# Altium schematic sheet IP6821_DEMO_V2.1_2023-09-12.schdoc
size 298 x 183 mm
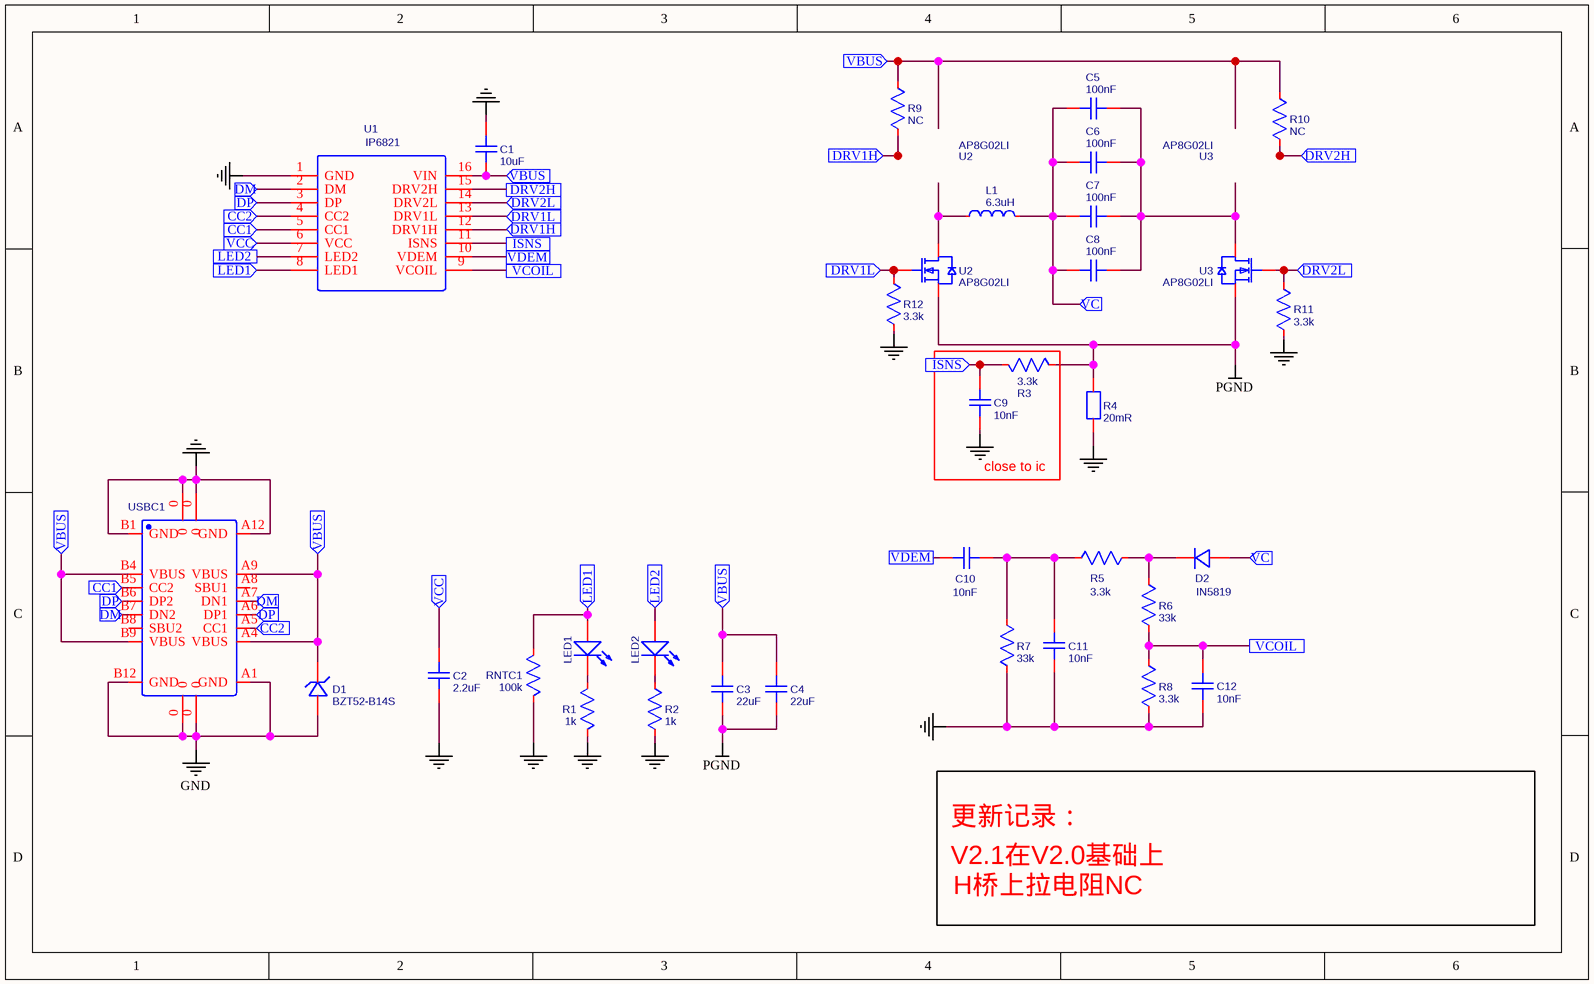
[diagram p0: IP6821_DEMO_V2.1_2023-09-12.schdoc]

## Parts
(Parts that share a designator on the sheet are numbered #1, #2 ... from top to bottom, then left to right.)
C1  10uF  [C0603]
C2  2.2uF  [C0603]
C3  22uF  [C0805]
C4  22uF  [C0805]
C5  100nF  [C1206]
C6  100nF  [C1206]
C7  100nF  [C1206]
C8  100nF  [C1206]
C9  10nF  [C0603]
C10  10nF  [C0603]
C11  10nF  [C0603]
C12  10nF  [C0603]
D1  BZT52-B14S  [SOD-323_L1.9-W1.3-LS2.5-RD-1]
D2  IN5819  [SOD-123_L2.7-W1.6-LS3.7-R-RD]
L1  6.3uH  [IND-SMD_L4.5-W3.0]
LED1  LED  [LED0603_RED]  (value not drawn)
LED2  LED  [LED0603_GREEN]  (value not drawn)
R1  1k  [R0603]
R2  1k  [R0603]
R3  3.3k  [R0603]
R4  20mR  [R1206]
R5  3.3k  [R0603]
R6  33k  [R0603]
R7  33k  [R0603]
R8  3.3k  [R0603]
R9  NC  [R0603]
R10  NC  [R0603]
R11  3.3k  [R0603]
R12  3.3k  [R0603]
RNTC1  100k  [R0603]
U1  IP6821  [SOP-16_L9.9-W3.9-P1.27-LS6.0-BL]
U2#1  AP8G02LI  [SOT-23-6_L2.9-W1.6-P0.95-LS2.7-BL]
U2#2  AP8G02LI  [SOT-23-6_L2.9-W1.6-P0.95-LS2.7-BL]
U3#1  AP8G02LI  [SOT-23-6_L2.9-W1.6-P0.95-LS2.7-BL]
U3#2  AP8G02LI  [SOT-23-6_L2.9-W1.6-P0.95-LS2.7-BL]
USBC1  TYPE-C-31-M-12  [USB-C_SMD-TYPE-C-31-M-12]  (value not drawn)

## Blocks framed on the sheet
close to ic: C9 R3

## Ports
CC1 (in), CC2 (in), DM (in), DP (in), DRV1H (in), DRV1L (in), DRV2H (in), DRV2L (in), ISNS (in), LED1 (in), LED2 (in), VBUS (in), VC (in), VCC (in), VCOIL (in), VDEM (in)

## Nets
GND: C1.2 C2.1 C9.1 C11.1 C12.1 D1.2(A) R1.1 R2.1 R4.2 R7.1 R8.1 R11.1 R12.1 RNTC1.1 U1.1(GND) USBC1.0 USBC1.A1(GND) USBC1.A12(GND) USBC1.B1(GND) USBC1.B12(GND)
PGND: C3.1 C4.1 R3.1 R4.1 U2#2.5(S) U3#2.5(S)
CC1: U1.5(CC1) USBC1.B5(CC2) ; port CC1
CC2: U1.4(CC2) USBC1.A5(CC1) ; port CC2
DM: U1.2(DM) USBC1.A7(DN1) USBC1.B7(DN2) ; port DM
DP: U1.3(DP) USBC1.A6(DP1) USBC1.B6(DP2) ; port DP
DRV1H: R9.1 U1.12(DRV1H) ; port DRV1H
DRV1L: R12.2 U1.13(DRV1L) U2#2.1(G) ; port DRV1L
DRV2H: R10.1 ; port DRV2H
DRV2L: R11.2 U1.14(DRV2L) U3#2.1(G) ; port DRV2L
ISNS: C9.2 R3.2 ; port ISNS
LED1: LED1.1(A) RNTC1.2 U1.8(LED1) ; port LED1
LED2: LED2.1(A) ; port LED2
VBUS: C1.1 C3.2 C4.2 D1.1(C) R9.2 R10.2 U1.16(VIN) USBC1.A4(VBUS) USBC1.A9(VBUS) USBC1.B4(VBUS) USBC1.B9(VBUS) ; port VBUS
VC: C5.1 C6.1 C7.1 C8.1 D2.1(A) L1.2 ; port VC
VCC: C2.2 U1.6(VCC) ; port VCC
NetC5_2: C5.2 C6.2 C7.2 C8.2 U3#2.6(D)
NetC10_2: C10.2 C11.2 R5.1 R7.2
NetC12_2: C12.2 R6.1 R8.2
NetD2_2: D2.2(K) R5.2 R6.2
NetL1_1: L1.1 U2#2.6(D)
NetLED1_2: LED1.2(K) R1.2
NetLED2_2: LED2.2(K) R2.2

Not connected (* = marked no-connect by the designer): C10 1; U1 7(LED2) 9(VCOIL) 10(VDEM) 11(ISNS) 15(DRV2H); USBC1 A8(SBU1) B8(SBU2)

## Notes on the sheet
- 更新记录：
- V2.1在V2.0基础上
- H桥上拉电阻NC

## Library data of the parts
C1 = 10uF: nameAlias: Value(F); Contributor: LCEDA_Lib
C2 = 2.2uF: nameAlias: Value(F); Contributor: LCEDA_Lib
C3 C4 = 22uF: nameAlias: Value(F); Contributor: LCEDA_Lib
C5-C8 = 100nF: Manufacturer: YAGEO; Manufacturer Part: CC1206KRX7R9BB104; nameAlias: Capacitance
C9-C12 = 10nF: nameAlias: Value(F); Contributor: LCEDA_Lib
D1 = BZT52-B14S: Manufacturer: PANJIT(强茂); Manufacturer Part: BZT52-B14S_R1_00001; Contributor: LCSC
D2 = IN5819: Manufacturer Part: 1N5819W; Contributor: LCSC
L1 = 6.3uH: Manufacturer: Sunlord; Manufacturer Part: MPH252012S4R7MT; nameAlias: Inductance
LED1 LED2 = LED: Contributor: tycc
R1 R2 = 1k: nameAlias: Value(Ω); Contributor: LCEDA_Lib
R3 R5 R8 R11 R12 = 3.3k: nameAlias: Value(Ω); Contributor: LCEDA_Lib
R4 = 20mR: nameAlias: Value(Ω); Contributor: LCEDA_Lib; Package Display: No
R6 R7 = 33k: nameAlias: Value(Ω); Contributor: LCEDA_Lib
R9 R10 = NC: nameAlias: Value(Ω); Contributor: LCEDA_Lib
RNTC1 = 100k: nameAlias: Value(Ω); Contributor: LCEDA_Lib
U1 = IP6821: Manufacturer: Injoinic; Contributor: it173; Package Display: No
USBC1 = TYPE-C-31-M-12: Manufacturer: Rectangular Connectors - Contacts; Contributor: LCSC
